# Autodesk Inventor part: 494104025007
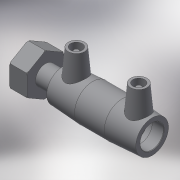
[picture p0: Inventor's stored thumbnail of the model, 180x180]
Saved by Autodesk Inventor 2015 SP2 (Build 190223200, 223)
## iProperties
Created: 2017-06
Part Number: 494104025007
Material: Generic
Description: PLASSON FEMALE FREE NUT TRANSITION COUPLER 25-3/4"
Document SubType Name: Modeling
Designer: KIM
Mass: 55.0731 g
Surface Area: 148.067 cm^2
Volume: 55.0731 cm^3
Density: 1 g/cm^3
Appearance: Default
Author: KIM
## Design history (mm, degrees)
derived "494104.ipt"
feature "Solid1::494104.ipt"
tag "TaggingFeature1"
body "Solid1"
other parameters: "d0" = 82, "d1" = 25, "d2" = 36, "d4" = 27.33333, "d5" = 32.4, "d6" = 23.75, "d7" = 25, "d8" = 168 deg, "d10" = 16, "d11" = 5.33333, "d29" = 37, "d30" = 14, "d31" = 28.7, "d34" = 5 deg, "d41" = 4, "d42" = 14, "d43" = 0, "d48" = 3, "d49" = 0, "d57" = 14, "d80" = 0.5, "d83" = 15, "d84" = 9.9, "d85" = 0.99, "d86" = 19.2936, "d87" = 24.117, "d88" = 36.1755, "d89" = 36, "d90" = 0.72351, "d94" = 0, "d95" = 0.99, "d96" = 16.8819, "d_" = 25, "L_" = 112, "D_1" = 36, "A_" = 37, "d_2" = 12, "D_" = 14, "G_" = 24.117
